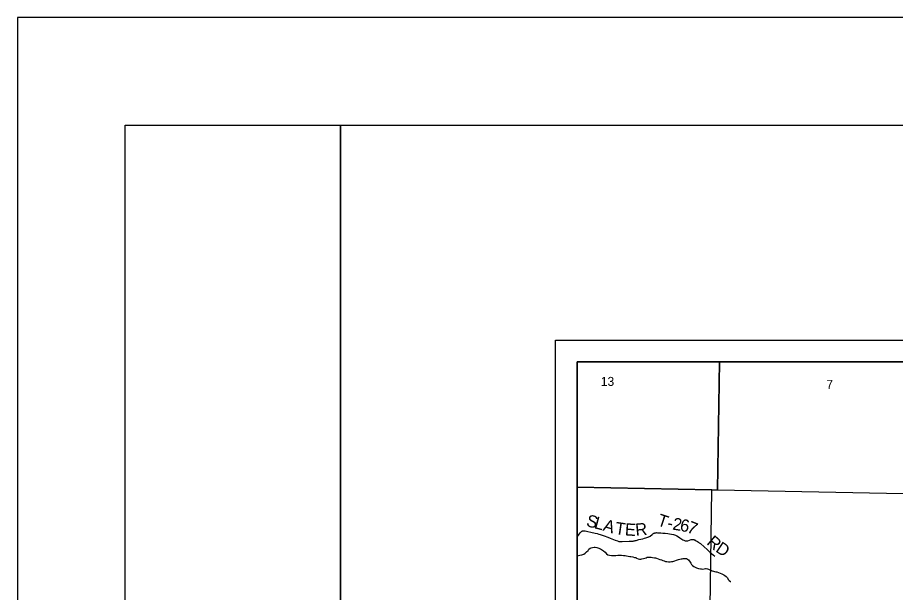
# Model space of a CAD drawing. Extents: x 0 to 34, y 0 to 22.
# Drawn here: x 0 to 4.079, y 19.327 to 22 of the extents above; entities that cross this region are included whole.
import ezdxf

# ---------------------------------------------------------------- set-up
doc = ezdxf.new("R2010")
doc.units = 0
for name, color, linetype in [('GM_X_Corporation', 7, 'Continuous'), ('GM_X_Minor_River', 7, 'Continuous'), ('GM_X_Section_Text', 7, 'Continuous'), ('GM_X_Township_Road', 7, 'Continuous'), ('GM_X_Township_Road_Text', 7, 'Continuous'), ('SH_Border', 7, 'Continuous'), ('SH_Cut_Line', 7, 'Continuous'), ('SH_Data', 7, 'Continuous')]:
    doc.layers.add(name, color=color, linetype=linetype)

msp = doc.modelspace()

# ---------------------------------------------------------------- linework, layer by layer
at = {"layer": 'GM_X_Corporation'}
for points in [[(9.4, 16.4853), (9.4, 20.4), (2.6, 20.4), (2.6, 16.6918), (3.1555, 16.6686), (3.1684, 16.6682), (4.0515, 16.6368), (4.1011, 16.6362), (4.1867, 16.6352), (4.5473, 16.6256), (4.6351, 16.6229), (5.4202, 16.5982), (6.0834, 16.5816), (6.2194, 16.578), (8.0963, 16.5226), (9.09, 16.4927)], [(3.2614, 20.4), (2.6, 20.4), (2.6, 19.8164), (3.226, 19.805), (3.2518, 19.8039)], [(6.2895, 20.4), (2.6, 20.4), (2.6, 16.6918), (3.1555, 16.6686), (3.1684, 16.6682), (4.0515, 16.6368), (4.1011, 16.6362), (4.1867, 16.6352), (4.5473, 16.6256), (4.6351, 16.6229), (5.4202, 16.5982), (6.0834, 16.5816), (6.2194, 16.578), (6.2729, 18.2077), (6.2744, 18.4654), (6.2786, 18.5898), (6.292, 18.5898), (6.2926, 19.1539), (6.2942, 19.6131), (6.2595, 19.6124)], [(4.2908, 20.4), (3.2614, 20.4), (3.2518, 19.8039), (4.2724, 19.7849), (4.2853, 19.7839)], [(2.6, 19.8164), (2.6, 18.7322), (3.2101, 18.7098), (3.226, 19.805)], [(3.2518, 19.8039), (4.2724, 19.7849), (4.2417, 18.6679), (3.2101, 18.7098), (3.226, 19.805)]]:
    msp.add_lwpolyline(points, close=True, dxfattribs=at)
at = {"layer": 'GM_X_Minor_River'}
for points in [[(2.6, 19.497), (2.6063, 19.4988), (2.6124, 19.5), (2.6218, 19.5027), (2.6259, 19.5039), (2.6316, 19.5059), (2.638, 19.5101), (2.6444, 19.5162), (2.6515, 19.5231), (2.6552, 19.5284), (2.6608, 19.5338), (2.6661, 19.535), (2.6717, 19.5369), (2.6793, 19.5377), (2.6842, 19.5378), (2.6918, 19.5367), (2.696, 19.5353), (2.7089, 19.5301), (2.7226, 19.5208), (2.7307, 19.5141), (2.7364, 19.5065), (2.7433, 19.5028), (2.7505, 19.5003), (2.76, 19.4996), (2.7797, 19.4998), (2.7887, 19.5006), (2.802, 19.5008), (2.8065, 19.5005), (2.8152, 19.4998), (2.8228, 19.4991), (2.8289, 19.4973), (2.838, 19.4962), (2.8444, 19.4948), (2.8501, 19.4941), (2.8585, 19.4923), (2.8672, 19.4905), (2.8725, 19.4894), (2.8767, 19.4868), (2.8839, 19.4842), (2.8896, 19.482), (2.8961, 19.4817), (2.9013, 19.4833), (2.9085, 19.4845)], [(2.9085, 19.4845), (2.9149, 19.4872), (2.9213, 19.4884), (2.9259, 19.4907), (2.9323, 19.4919), (2.938, 19.4916), (2.9448, 19.4913), (2.9508, 19.4902), (2.9592, 19.4888), (2.9649, 19.4881), (2.9691, 19.4862), (2.9767, 19.4844), (2.9846, 19.48), (2.9915, 19.4785), (2.998, 19.4752), (3.0052, 19.4737), (3.0105, 19.4715), (3.0169, 19.4708), (3.0241, 19.4698), (3.0332, 19.4702), (3.0385, 19.471), (3.0445, 19.4715), (3.0491, 19.4734), (3.0547, 19.4746), (3.0623, 19.4781), (3.0713, 19.4808), (3.0777, 19.4824), (3.0838, 19.4832), (3.0879, 19.4833), (3.0928, 19.4845), (3.1042, 19.4853), (3.1084, 19.485), (3.1137, 19.4816), (3.1183, 19.479), (3.1252, 19.4678), (3.1283, 19.4636), (3.1314, 19.4572), (3.136, 19.4524), (3.1425, 19.4475), (3.1489, 19.4449), (3.155, 19.4416), (3.1645, 19.4387), (3.1736, 19.4373), (3.1786, 19.4366), (3.1842, 19.4362), (3.191, 19.4371), (3.1959, 19.4382), (3.2005, 19.4383), (3.2062, 19.4368), (3.2104, 19.4354), (3.2168, 19.4328), (3.2218, 19.4309), (3.2275, 19.4284), (3.2339, 19.4269), (3.2389, 19.4255), (3.2449, 19.424), (3.2499, 19.4225), (3.2567, 19.42), (3.2643, 19.417), (3.2727, 19.4133), (3.2811, 19.4092), (3.2868, 19.4055), (3.2933, 19.4011), (3.2983, 19.3951), (3.3021, 19.3883), (3.3071, 19.3827), (3.3136, 19.3786), (3.3148, 19.3781)]]:
    msp.add_lwpolyline(points, dxfattribs=at)
at = {"layer": 'GM_X_Township_Road'}
for points in [[(2.6, 19.5853), (2.6021, 19.5874), (2.6069, 19.5931), (2.61, 19.598), (2.6144, 19.6045), (2.6158, 19.6066), (2.6171, 19.6081), (2.6186, 19.6094), (2.6202, 19.6106), (2.6218, 19.6117), (2.6232, 19.6125), (2.625, 19.6132), (2.6268, 19.6138), (2.6284, 19.614), (2.6302, 19.6141), (2.6322, 19.614), (2.6342, 19.6139), (2.6371, 19.6134), (2.6499, 19.6102), (2.6642, 19.6074), (2.6844, 19.6033), (2.6939, 19.6011), (2.7013, 19.5991), (2.707, 19.5973), (2.7124, 19.5951), (2.7205, 19.592), (2.7256, 19.5902), (2.7423, 19.5842), (2.754, 19.5796), (2.7768, 19.5708), (2.7877, 19.5668), (2.7909, 19.5658), (2.7942, 19.5649), (2.7968, 19.5643), (2.7993, 19.5639), (2.8019, 19.5637), (2.805, 19.5635), (2.8102, 19.5637), (2.842, 19.5653), (2.8459, 19.5653), (2.8574, 19.566), (2.8611, 19.5665), (2.8639, 19.567), (2.8669, 19.5676), (2.8702, 19.5684), (2.8739, 19.5695), (2.8864, 19.5728), (2.8962, 19.5749), (2.9048, 19.5771), (2.9134, 19.5795), (2.92, 19.5815)], [(2.92, 19.5815), (2.9247, 19.5829), (2.9287, 19.5843), (2.9314, 19.5854), (2.9339, 19.5865), (2.9361, 19.5877), (2.9388, 19.5895), (2.9489, 19.5975), (2.9523, 19.5998), (2.9548, 19.6015), (2.9571, 19.6026), (2.9592, 19.6034), (2.9615, 19.6041), (2.9642, 19.6047), (2.9668, 19.6051), (2.9697, 19.6054), (2.9739, 19.6053), (2.9803, 19.6048), (2.9896, 19.6042), (2.9981, 19.6035), (3.009, 19.6024), (3.0212, 19.6009), (3.0294, 19.5999), (3.0383, 19.5985), (3.0475, 19.5967), (3.0533, 19.5952), (3.0566, 19.594), (3.0599, 19.5925), (3.0636, 19.5904), (3.0707, 19.5855), (3.0769, 19.5811), (3.0817, 19.5777), (3.0866, 19.5746), (3.0914, 19.572), (3.0956, 19.57), (3.099, 19.5686), (3.1023, 19.5677), (3.1054, 19.5671), (3.1084, 19.567), (3.1115, 19.5672), (3.1147, 19.5678), (3.1306, 19.5728), (3.1327, 19.5733), (3.1348, 19.5735), (3.1403, 19.5734), (3.142, 19.5731), (3.1444, 19.5722), (3.1466, 19.5713), (3.1493, 19.57), (3.1527, 19.5681), (3.1564, 19.5661), (3.1599, 19.5639), (3.1638, 19.5613), (3.1672, 19.5588), (3.173, 19.5543), (3.1902, 19.5392), (3.204, 19.5271), (3.214, 19.5176), (3.219, 19.5132), (3.2328, 19.5024), (3.2405, 19.4968)]]:
    msp.add_lwpolyline(points, dxfattribs=at)
at = {"layer": 'SH_Border'}
for points in [[(0.5, 21.5), (1.5, 21.5), (1.5, 0.5), (0.5, 0.5)], [(1.5, 21.5), (33.5, 21.5), (33.5, 0.5), (1.5, 0.5)]]:
    msp.add_lwpolyline(points, close=True, dxfattribs=at)
at = {"layer": 'SH_Cut_Line'}
msp.add_lwpolyline([(0, 0), (34, 0), (34, 22), (0, 22)], close=True, dxfattribs=at)
at = {"layer": 'SH_Data'}
for points in [[(2.5, 20.5), (9.5, 20.5), (9.5, 13.5), (2.5, 13.5)], [(2.6, 20.4), (9.4, 20.4), (9.4, 13.6), (2.6, 13.6)]]:
    msp.add_lwpolyline(points, close=True, dxfattribs=at)

# ---------------------------------------------------------------- texts
at = {"layer": 'GM_X_Section_Text'}
for s, height, p in [('13', 0.04186, (2.71, 20.2875)), ('7', 0.0419, (3.7583, 20.2739))]:
    msp.add_text(s, height=height, rotation=0, dxfattribs=at).set_placement(p)
at = {"layer": 'GM_X_Township_Road_Text'}
for s, rotation, p in [('S', 345.8221, (2.6393, 19.6361)), ('L', 345.1842, (2.6763, 19.6267)), ('A', 343.1467, (2.7169, 19.616)), ('T', 341.8911, (2.9687, 19.6404)), ('2', 350.3891, (3.0408, 19.6201)), ('6', 349.751, (3.0752, 19.6142)), ('T', 351.7245, (2.7738, 19.5995)), ('E', 356.3517, (2.8209, 19.5928)), ('R', 5.6142, (2.8733, 19.5903)), ('-', 347.8028, (3.0153, 19.6255)), ('7', 338.1728, (3.1067, 19.6089)), ('R', 319.5949, (3.1985, 19.5544)), ('D', 326.2742, (3.2397, 19.5198))]:
    msp.add_text(s, height=0.0568, rotation=rotation, dxfattribs=at).set_placement(p)

doc.saveas('drawing.dxf')
